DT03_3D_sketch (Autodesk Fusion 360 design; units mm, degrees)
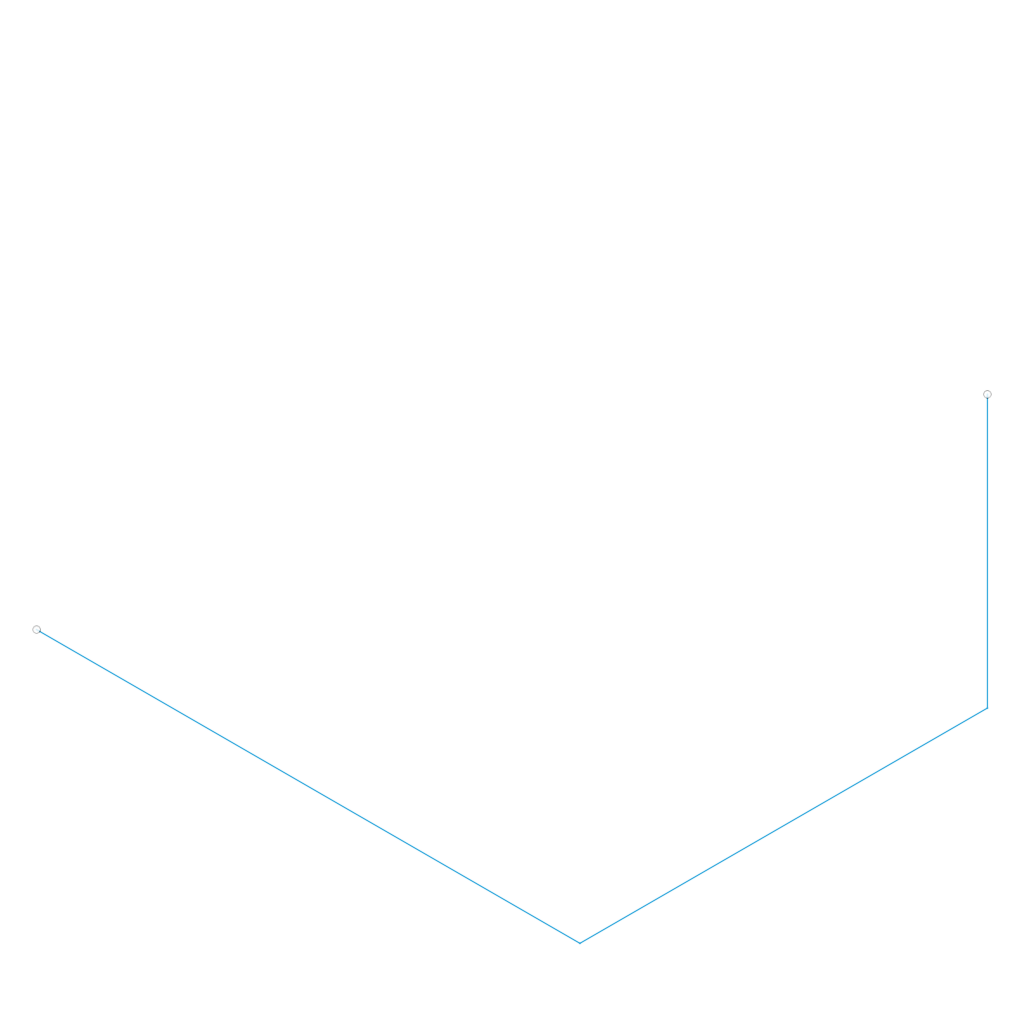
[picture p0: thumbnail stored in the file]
part number: 2026-10-26-12-17-31-515
parameter "OD_DEMO_ONLY_1_5_x_095_R6" = 38.1
parameter "Wall_DEMO_ONLY_1_5_x_095_R6" = 2.413
sketch "Tube points" plane through (0, 0, 0) normal (0, 0, 1) x axis (1, 0, 0)
sketch "TubePoints" plane through (0, 0, 0) normal (0, 0, 1) x axis (1, 0, 0)
work_plane "WorkPlane1" ExtraOffset 0
sketch "Sketch3" plane through (0, 203.2, 0) normal (1, 0, 0) x axis (0, 0, 1)
  circle C1 centre (0, 0) radius 19.05
  circle C2 centre (0, 0) radius 16.637
  dimension "d5" diameter C1 = 38.1 (= "OD_DEMO_ONLY_1_5_x_095_R6")
  dimension "d6" diameter C2 = 33.274 (= "OD_DEMO_ONLY_1_5_x_095_R6 - 2 * Wall_DEMO_ONLY_1_5_x_095_R6")
sweep "Sweep1" sketch "Sketch3" TwistAngle 0 TaperAngle 0 bodies "P1 Mirrored point tube"
sketch "TubePoints-m" plane through (0, 0, 0) normal (0, 0, 1) x axis (1, 0, 0)
work_plane "WorkPlane2" ExtraOffset 0
sketch "Sketch5" plane through (0, -203.2, 0) normal (1, 0, 0) x axis (0, 0, 1)
  circle C1 centre (0, 0) radius 19.05
  circle C2 centre (0, 0) radius 16.637
  dimension "d15" diameter C1 = 38.1 (= "OD_DEMO_ONLY_1_5_x_095_R6")
  dimension "d16" diameter C2 = 33.274 (= "OD_DEMO_ONLY_1_5_x_095_R6 - 2 * Wall_DEMO_ONLY_1_5_x_095_R6")
sweep "Sweep2" sketch "Sketch5" TwistAngle 0 TaperAngle 0 bodies "P2 Mirrored point tube"
sketch "3D practice frame" plane through (0, 0, 0) normal (0, 0, 1) x axis (1, 0, 0)
  line L1 (609.6, 0) -> (0, 0)
  line L2 (609.6, 457.2) -> (609.6, 0)
  line L3 (609.6, 457.2) -> (609.6, 457.2)
named bodies: "P1 Mirrored point tube", "P2 Mirrored point tube"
